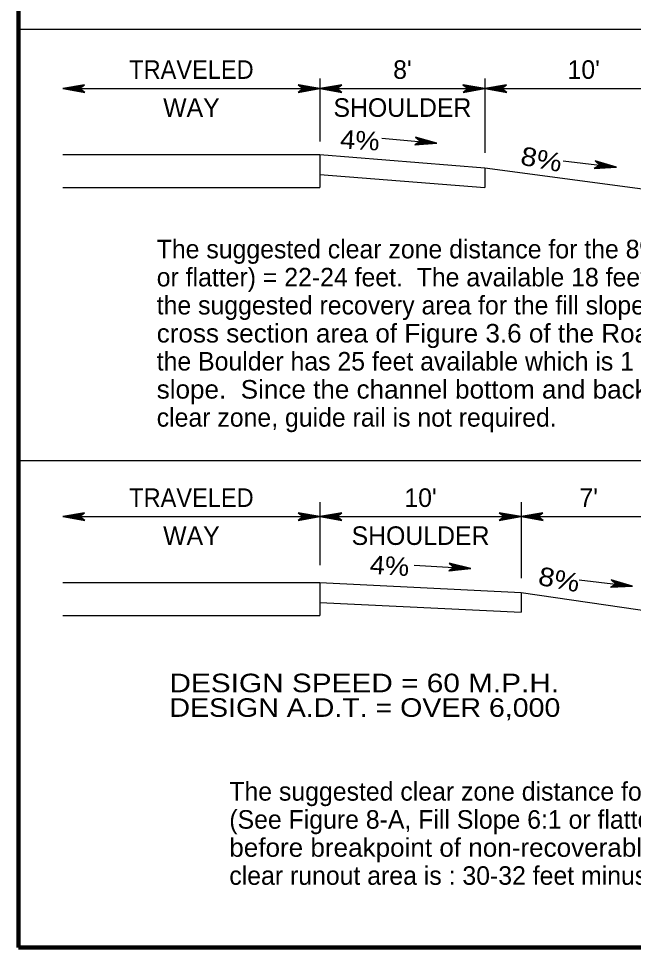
# Model space of a CAD drawing. Extents: x -15.691 to -15.016, y -14.8 to -13.916.
# Drawn here: x -15.6451 to -15.3861, y -14.7538 to -14.3626 of the extents above; entities that cross this region are included whole.
import ezdxf
from ezdxf.enums import TextEntityAlignment as Align

# ---------------------------------------------------------------- set-up
doc = ezdxf.new("R2010")
doc.units = 0
doc.header["$LTSCALE"] = 0.0031
for name, color, linetype, lineweight in [('1', 7, 'Continuous', 90), ('24', 7, 'Continuous', 25), ('5', 7, 'Continuous', 25)]:
    doc.layers.add(name, color=color, linetype=linetype, lineweight=lineweight)

msp = doc.modelspace()

# ---------------------------------------------------------------- linework, layer by layer
at = {"layer": '1'}
for p, q in [((-15.645142, -14.753775), (-15.645142, -13.962108)), ((-15.645142, -14.753775), (-15.645142, -13.962108)), ((-15.061808, -14.753775), (-15.645142, -14.753775))]:
    msp.add_line(p, q, dxfattribs=at)
at = {"layer": '24'}
for p, q in [((-15.518158, -14.387742), (-15.518158, -14.414308)), ((-15.448717, -14.387742), (-15.448717, -14.419075)), ((-15.492058, -14.412942), (-15.4689, -14.414983)), ((-15.415775, -14.422475), (-15.3933, -14.4252)), ((-15.518158, -14.5662), (-15.518158, -14.592758)), ((-15.433433, -14.5662), (-15.433433, -14.598208)), ((-15.626492, -14.572342), (-15.518158, -14.572342)), ((-15.478433, -14.592758), (-15.4546, -14.594125)), ((-15.408967, -14.598892), (-15.386492, -14.601617))]:
    msp.add_line(p, q, dxfattribs=at)
for points in [[(-15.626492, -14.392042), (-15.61725, -14.393675), (-15.619458, -14.392042), (-15.6173, -14.390433), (-15.626492, -14.392042), (-15.625875, -14.392025), (-15.617508, -14.39355), (-15.619633, -14.392017), (-15.617675, -14.390558), (-15.62555, -14.391992), (-15.625242, -14.392042), (-15.618075, -14.393308), (-15.619683, -14.392017), (-15.618025, -14.390767), (-15.6251, -14.392042), (-15.624792, -14.391992), (-15.618525, -14.393125), (-15.619742, -14.392042), (-15.6185, -14.390908), (-15.6239, -14.391992), (-15.623375, -14.391992), (-15.618992, -14.392892), (-15.619842, -14.392067), (-15.618925, -14.391142), (-15.623283, -14.392042), (-15.622792, -14.392067), (-15.619492, -14.392633), (-15.620125, -14.391992), (-15.619442, -14.391358), (-15.622342, -14.392042), (-15.621875, -14.392083), (-15.619892, -14.392467), (-15.620217, -14.392017), (-15.619675, -14.391525), (-15.621633, -14.392042), (-15.620342, -14.392342), (-15.620525, -14.391992), (-15.619958, -14.391642), (-15.621308, -14.391992), (-15.620458, -14.3922), (-15.620817, -14.391925), (-15.620408, -14.391758), (-15.620817, -14.392017), (-15.6206, -14.392067)], [(-15.626492, -14.392042), (-15.518158, -14.392042), (-15.448717, -14.392042)], [(-15.518158, -14.392042), (-15.5274, -14.390408), (-15.525192, -14.392042), (-15.52735, -14.39365), (-15.518158, -14.392042), (-15.518775, -14.392058), (-15.527142, -14.390525), (-15.525017, -14.392058), (-15.526975, -14.393517), (-15.5191, -14.392083), (-15.519408, -14.392042), (-15.526583, -14.390767), (-15.524975, -14.392058), (-15.526625, -14.393308), (-15.51955, -14.392042), (-15.519858, -14.392083), (-15.526125, -14.39095), (-15.524908, -14.392042), (-15.52615, -14.393167), (-15.52075, -14.392083), (-15.521275, -14.392083), (-15.525658, -14.391183), (-15.524808, -14.392008), (-15.525725, -14.392933), (-15.521367, -14.392042), (-15.521858, -14.392008), (-15.525158, -14.391442), (-15.524525, -14.392083), (-15.525208, -14.392717), (-15.522317, -14.392042), (-15.522775, -14.391992), (-15.524758, -14.391617), (-15.524433, -14.392058), (-15.524975, -14.39255), (-15.523017, -14.392033), (-15.524308, -14.391733), (-15.524125, -14.392083), (-15.524692, -14.392442), (-15.523342, -14.392083), (-15.524192, -14.391875), (-15.523833, -14.39215), (-15.524242, -14.392317), (-15.523842, -14.392058), (-15.52405, -14.392008)], [(-15.518158, -14.392042), (-15.508917, -14.393675), (-15.511125, -14.392042), (-15.508967, -14.390433), (-15.518158, -14.392042), (-15.517542, -14.392025), (-15.509175, -14.39355), (-15.5113, -14.392017), (-15.509342, -14.390558), (-15.517217, -14.391992), (-15.516908, -14.392042), (-15.509742, -14.393308), (-15.51135, -14.392017), (-15.509692, -14.390767), (-15.516767, -14.392042), (-15.516458, -14.391992), (-15.510192, -14.393125), (-15.511408, -14.392042), (-15.510167, -14.390908), (-15.515567, -14.391992), (-15.515042, -14.391992), (-15.510658, -14.392892), (-15.511508, -14.392067), (-15.510592, -14.391142), (-15.51495, -14.392042), (-15.514458, -14.392067), (-15.511158, -14.392633), (-15.511792, -14.391992), (-15.511108, -14.391358), (-15.514008, -14.392042), (-15.513542, -14.392083), (-15.511558, -14.392467), (-15.511883, -14.392017), (-15.511342, -14.391525), (-15.5133, -14.392042), (-15.512008, -14.392342), (-15.512192, -14.391992), (-15.511625, -14.391642), (-15.512975, -14.391992), (-15.512125, -14.3922), (-15.512483, -14.391925), (-15.512075, -14.391758), (-15.512475, -14.392017), (-15.512267, -14.392067)], [(-15.448717, -14.392042), (-15.457958, -14.390408), (-15.45575, -14.392042), (-15.457908, -14.39365), (-15.448717, -14.392042), (-15.449325, -14.392058), (-15.457692, -14.390525), (-15.455575, -14.392058), (-15.457533, -14.393517), (-15.449658, -14.392083), (-15.449967, -14.392042), (-15.457133, -14.390767), (-15.455525, -14.392058), (-15.457183, -14.393308), (-15.450108, -14.392042), (-15.450417, -14.392083), (-15.456683, -14.39095), (-15.455458, -14.392042), (-15.456708, -14.393167), (-15.451308, -14.392083), (-15.451825, -14.392083), (-15.456217, -14.391183), (-15.455358, -14.392008), (-15.456283, -14.392933), (-15.451925, -14.392042), (-15.452417, -14.392008), (-15.455717, -14.391442), (-15.455083, -14.392083), (-15.455767, -14.392717), (-15.452867, -14.392042), (-15.453333, -14.391992), (-15.455317, -14.391617), (-15.454992, -14.392058), (-15.455525, -14.39255), (-15.453575, -14.392033), (-15.454867, -14.391733), (-15.454683, -14.392083), (-15.45525, -14.392442), (-15.4539, -14.392083), (-15.45475, -14.391875), (-15.454392, -14.39215), (-15.4548, -14.392317), (-15.454392, -14.392058), (-15.454608, -14.392008)], [(-15.448717, -14.392042), (-15.439475, -14.393675), (-15.441683, -14.392042), (-15.439525, -14.390433), (-15.448717, -14.392042), (-15.4481, -14.392025), (-15.439733, -14.39355), (-15.441858, -14.392017), (-15.439892, -14.390558), (-15.447767, -14.391992), (-15.447458, -14.392042), (-15.440292, -14.393308), (-15.4419, -14.392017), (-15.44025, -14.390767), (-15.447325, -14.392042), (-15.447017, -14.391992), (-15.44075, -14.393125), (-15.441967, -14.392042), (-15.440725, -14.390908), (-15.446125, -14.391992), (-15.4456, -14.391992), (-15.441217, -14.392892), (-15.442067, -14.392067), (-15.44115, -14.391142), (-15.445508, -14.392042), (-15.445017, -14.392067), (-15.441717, -14.392633), (-15.44235, -14.391992), (-15.441658, -14.391358), (-15.444558, -14.392042), (-15.444092, -14.392083), (-15.442117, -14.392467), (-15.442442, -14.392017), (-15.4419, -14.391525), (-15.44385, -14.392042), (-15.442558, -14.392342), (-15.44275, -14.391992), (-15.442183, -14.391642), (-15.443525, -14.391992), (-15.442683, -14.3922), (-15.443033, -14.391925), (-15.442625, -14.391758), (-15.443033, -14.392017), (-15.442825, -14.392067)], [(-15.448717, -14.392042), (-15.365383, -14.392042), (-15.313992, -14.392042)], [(-15.4689, -14.414983), (-15.477958, -14.41255), (-15.475908, -14.414367), (-15.4782, -14.415783), (-15.4689, -14.414983), (-15.469517, -14.41495), (-15.477717, -14.412692), (-15.475733, -14.4144), (-15.477817, -14.415683), (-15.46985, -14.41495), (-15.47015, -14.414875), (-15.477175, -14.412975), (-15.475692, -14.414408), (-15.47745, -14.415508), (-15.470292, -14.414867), (-15.4706, -14.414883), (-15.476742, -14.413208), (-15.475625, -14.414392), (-15.476958, -14.415408), (-15.471492, -14.414808), (-15.472008, -14.414758), (-15.4763, -14.413475), (-15.475517, -14.414375), (-15.476517, -14.415208), (-15.472092, -14.414708), (-15.472583, -14.414633), (-15.475825, -14.413783), (-15.475242, -14.414475), (-15.475983, -14.415042), (-15.473042, -14.414625), (-15.4735, -14.414533), (-15.475442, -14.413983), (-15.47515, -14.414458), (-15.475733, -14.4149), (-15.473742, -14.414558), (-15.475, -14.414142), (-15.47485, -14.414508), (-15.475442, -14.414808), (-15.474067, -14.414575), (-15.4749, -14.414292), (-15.474567, -14.4146), (-15.474983, -14.414733), (-15.474558, -14.414508), (-15.474767, -14.414442)], [(-15.3933, -14.4252), (-15.402275, -14.422467), (-15.400283, -14.424358), (-15.402617, -14.425692), (-15.3933, -14.4252), (-15.393908, -14.42515), (-15.402033, -14.422625), (-15.400117, -14.4244), (-15.402233, -14.425608), (-15.394242, -14.425133), (-15.394542, -14.42505), (-15.401508, -14.422925), (-15.400067, -14.4244), (-15.401858, -14.42545), (-15.394683, -14.425033), (-15.394992, -14.425042), (-15.401075, -14.423167), (-15.4, -14.424392), (-15.401367, -14.425358), (-15.395883, -14.424933), (-15.3964, -14.424875), (-15.400642, -14.423458), (-15.3999, -14.424375), (-15.400917, -14.425175), (-15.396483, -14.424817), (-15.396967, -14.424733), (-15.400175, -14.423775), (-15.399625, -14.424483), (-15.400383, -14.425025), (-15.397425, -14.4247), (-15.397883, -14.4246), (-15.3998, -14.423983), (-15.399533, -14.424467), (-15.400125, -14.424892), (-15.398125, -14.424617), (-15.399367, -14.424158), (-15.399225, -14.424533), (-15.399833, -14.424817), (-15.39845, -14.424625), (-15.399267, -14.424317), (-15.39895, -14.424633), (-15.399375, -14.42475), (-15.398942, -14.424542), (-15.39915, -14.424467)], [(-15.626492, -14.572342), (-15.61725, -14.573975), (-15.619458, -14.572342), (-15.6173, -14.570733), (-15.626492, -14.572342), (-15.625875, -14.572317), (-15.617508, -14.57385), (-15.619633, -14.572317), (-15.617675, -14.570858), (-15.62555, -14.572292), (-15.625242, -14.572342), (-15.618075, -14.573608), (-15.619683, -14.572317), (-15.618025, -14.571067), (-15.6251, -14.572342), (-15.624792, -14.572292), (-15.618525, -14.573425), (-15.619742, -14.572342), (-15.6185, -14.571208), (-15.6239, -14.572292), (-15.623375, -14.572292), (-15.618992, -14.573192), (-15.619842, -14.572367), (-15.618925, -14.571442), (-15.623283, -14.572342), (-15.622792, -14.572367), (-15.619492, -14.572933), (-15.620125, -14.572292), (-15.619442, -14.571658), (-15.622342, -14.572342), (-15.621875, -14.572383), (-15.619892, -14.572767), (-15.620217, -14.572317), (-15.619675, -14.571825), (-15.621633, -14.572342), (-15.620342, -14.572642), (-15.620525, -14.572292), (-15.619958, -14.571942), (-15.621308, -14.572292), (-15.620458, -14.5725), (-15.620817, -14.572225), (-15.620408, -14.572058), (-15.620817, -14.572317), (-15.6206, -14.572367)], [(-15.518158, -14.572342), (-15.5274, -14.570708), (-15.525192, -14.572342), (-15.52735, -14.573942), (-15.518158, -14.572342), (-15.518775, -14.572358), (-15.527142, -14.570825), (-15.525017, -14.572358), (-15.526975, -14.573817), (-15.5191, -14.572383), (-15.519408, -14.572342), (-15.526583, -14.571067), (-15.524975, -14.572358), (-15.526625, -14.573608), (-15.51955, -14.572333), (-15.519858, -14.572383), (-15.526125, -14.57125), (-15.524908, -14.572333), (-15.52615, -14.573467), (-15.52075, -14.572383), (-15.521275, -14.572383), (-15.525658, -14.571483), (-15.524808, -14.572308), (-15.525725, -14.573233), (-15.521367, -14.572342), (-15.521858, -14.572308), (-15.525158, -14.571742), (-15.524525, -14.572383), (-15.525208, -14.573017), (-15.522317, -14.572342), (-15.522775, -14.572292), (-15.524758, -14.571908), (-15.524433, -14.572358), (-15.524975, -14.57285), (-15.523017, -14.572333), (-15.524308, -14.572033), (-15.524125, -14.572383), (-15.524692, -14.572742), (-15.523342, -14.572383), (-15.524192, -14.572175), (-15.523833, -14.57245), (-15.524242, -14.572617), (-15.523842, -14.572358), (-15.52405, -14.572308)], [(-15.518158, -14.572342), (-15.508917, -14.573975), (-15.511125, -14.572342), (-15.508967, -14.570733), (-15.518158, -14.572342), (-15.517542, -14.572317), (-15.509175, -14.57385), (-15.5113, -14.572317), (-15.509342, -14.570858), (-15.517217, -14.572292), (-15.516908, -14.572342), (-15.509742, -14.573608), (-15.51135, -14.572317), (-15.509692, -14.571067), (-15.516767, -14.572342), (-15.516458, -14.572292), (-15.510192, -14.573425), (-15.511408, -14.572342), (-15.510167, -14.571208), (-15.515567, -14.572292), (-15.515042, -14.572292), (-15.510658, -14.573192), (-15.511508, -14.572367), (-15.510592, -14.571442), (-15.51495, -14.572342), (-15.514458, -14.572367), (-15.511158, -14.572933), (-15.511792, -14.572292), (-15.511108, -14.571658), (-15.514008, -14.572342), (-15.513542, -14.572383), (-15.511558, -14.572767), (-15.511883, -14.572317), (-15.511342, -14.571825), (-15.5133, -14.572342), (-15.512008, -14.572642), (-15.512192, -14.572292), (-15.511625, -14.571942), (-15.512975, -14.572292), (-15.512125, -14.5725), (-15.512483, -14.572225), (-15.512075, -14.572058), (-15.512475, -14.572317), (-15.512267, -14.572367)], [(-15.518158, -14.572342), (-15.433433, -14.572342), (-15.376492, -14.572342), (-15.277883, -14.572342), (-15.168158, -14.572342)], [(-15.433433, -14.572342), (-15.442675, -14.570708), (-15.440467, -14.572342), (-15.442625, -14.573942), (-15.433433, -14.572342), (-15.43405, -14.572358), (-15.442417, -14.570825), (-15.4403, -14.572358), (-15.442258, -14.573817), (-15.434383, -14.572383), (-15.434692, -14.572342), (-15.441858, -14.571067), (-15.44025, -14.572358), (-15.4419, -14.573608), (-15.434833, -14.572333), (-15.435133, -14.572383), (-15.4414, -14.57125), (-15.440183, -14.572333), (-15.441425, -14.573467), (-15.436033, -14.572383), (-15.43655, -14.572383), (-15.440942, -14.571483), (-15.440083, -14.572308), (-15.441, -14.573233), (-15.436642, -14.572342), (-15.437133, -14.572308), (-15.440433, -14.571742), (-15.4398, -14.572383), (-15.440492, -14.573017), (-15.437592, -14.572342), (-15.438058, -14.572292), (-15.440033, -14.571908), (-15.439708, -14.572358), (-15.44025, -14.57285), (-15.4383, -14.572333), (-15.439592, -14.572033), (-15.4394, -14.572383), (-15.439967, -14.572742), (-15.438625, -14.572383), (-15.439467, -14.572175), (-15.439117, -14.57245), (-15.439525, -14.572617), (-15.439117, -14.572358), (-15.439333, -14.572308)], [(-15.433433, -14.572342), (-15.4242, -14.573975), (-15.4264, -14.572342), (-15.424242, -14.570733), (-15.433433, -14.572342), (-15.432825, -14.572317), (-15.424458, -14.57385), (-15.426575, -14.572317), (-15.424617, -14.570858), (-15.432492, -14.572292), (-15.432183, -14.572342), (-15.425017, -14.573608), (-15.426625, -14.572317), (-15.424967, -14.571067), (-15.432042, -14.572342), (-15.431733, -14.572292), (-15.425467, -14.573425), (-15.426692, -14.572342), (-15.425442, -14.571208), (-15.430842, -14.572292), (-15.430325, -14.572292), (-15.425933, -14.573192), (-15.426792, -14.572367), (-15.425867, -14.571442), (-15.430233, -14.572342), (-15.429733, -14.572367), (-15.426433, -14.572933), (-15.427075, -14.572292), (-15.426383, -14.571658), (-15.429283, -14.572342), (-15.428817, -14.572383), (-15.426833, -14.572767), (-15.427167, -14.572317), (-15.426625, -14.571825), (-15.428575, -14.572342), (-15.427283, -14.572642), (-15.427467, -14.572292), (-15.4269, -14.571942), (-15.42825, -14.572292), (-15.4274, -14.5725), (-15.427758, -14.572225), (-15.42735, -14.572058), (-15.427758, -14.572317), (-15.427542, -14.572367)], [(-15.4546, -14.594125), (-15.463733, -14.591967), (-15.461617, -14.593725), (-15.463867, -14.5952), (-15.4546, -14.594125), (-15.455208, -14.5941), (-15.463475, -14.5921), (-15.46145, -14.59375), (-15.463483, -14.5951), (-15.455542, -14.594117), (-15.45585, -14.59405), (-15.462933, -14.592367), (-15.4614, -14.59375), (-15.463125, -14.594908), (-15.455992, -14.594042), (-15.4563, -14.594067), (-15.462492, -14.592583), (-15.461333, -14.593733), (-15.462642, -14.594792), (-15.457192, -14.594017), (-15.457708, -14.593992), (-15.462042, -14.592842), (-15.461233, -14.593717), (-15.4622, -14.594583), (-15.4578, -14.593942), (-15.458292, -14.593883), (-15.46155, -14.593133), (-15.460958, -14.593808), (-15.461675, -14.5944), (-15.458742, -14.593883), (-15.459208, -14.593808), (-15.461167, -14.593325), (-15.460867, -14.593783), (-15.461433, -14.59425), (-15.45945, -14.593842), (-15.460725, -14.593467), (-15.460558, -14.593825), (-15.461142, -14.59415), (-15.459775, -14.593875), (-15.460608, -14.593617), (-15.460275, -14.593908), (-15.460692, -14.594058), (-15.460267, -14.593817), (-15.460483, -14.593758)], [(-15.386492, -14.601617), (-15.395467, -14.598883), (-15.393475, -14.600767), (-15.395808, -14.602108), (-15.386492, -14.601617), (-15.3871, -14.601558), (-15.395225, -14.599033), (-15.3933, -14.600808), (-15.395425, -14.602025), (-15.387433, -14.601542), (-15.387733, -14.601467), (-15.394692, -14.599333), (-15.393258, -14.600817), (-15.39505, -14.601858), (-15.387875, -14.601442), (-15.388183, -14.601458), (-15.394267, -14.599575), (-15.393183, -14.6008), (-15.394558, -14.601775), (-15.389067, -14.60135), (-15.389583, -14.601283), (-15.393833, -14.599867), (-15.393083, -14.600792), (-15.394108, -14.601592), (-15.389675, -14.601225), (-15.390158, -14.601142), (-15.393367, -14.600183), (-15.392817, -14.600892), (-15.393575, -14.601442), (-15.390617, -14.601117), (-15.391067, -14.601008), (-15.392992, -14.6004), (-15.392717, -14.600875), (-15.393317, -14.6013), (-15.391317, -14.601025), (-15.392558, -14.600567), (-15.392417, -14.600942), (-15.393025, -14.601225), (-15.391642, -14.601033), (-15.392458, -14.600725), (-15.392142, -14.601042), (-15.392567, -14.601158), (-15.392133, -14.60095), (-15.392333, -14.600875)]]:
    msp.add_lwpolyline(points, dxfattribs=at)
at = {"layer": '5'}
for p, q in [((-15.645142, -14.367008), (-15.061808, -14.367008)), ((-15.626492, -14.419817), (-15.518158, -14.419817)), ((-15.518158, -14.419817), (-15.518158, -14.433708)), ((-15.448717, -14.425375), (-15.448717, -14.433733)), ((-15.518158, -14.428175), (-15.448717, -14.433733)), ((-15.626492, -14.433708), (-15.518158, -14.433708)), ((-15.645142, -14.5487), (-15.061808, -14.5487)), ((-15.626492, -14.600117), (-15.518158, -14.600117)), ((-15.518158, -14.600117), (-15.518158, -14.614008)), ((-15.433433, -14.604283), (-15.433433, -14.612625)), ((-15.518158, -14.608458), (-15.433433, -14.612625)), ((-15.626492, -14.614008), (-15.518158, -14.614008))]:
    msp.add_line(p, q, dxfattribs=at)
for points in [[(-15.518158, -14.419817), (-15.448717, -14.425375), (-15.365383, -14.436483), (-15.267042, -14.385983), (-15.239267, -14.385983)], [(-15.518158, -14.600117), (-15.433433, -14.604283), (-15.376492, -14.612617), (-15.277883, -14.644558), (-15.168158, -14.655675)]]:
    msp.add_lwpolyline(points, dxfattribs=at)

# ---------------------------------------------------------------- texts
at = {"layer": '1', "width": 0.95}
for p in [(-15.572321, -14.38795), (-15.572321, -14.56825)]:
    msp.add_text('TRAVELED', height=0.007817, dxfattribs=at).set_placement(p, align=Align.CENTER)
at = {"layer": '1'}
for s, p in [("8'", (-15.483433, -14.38795)), ("10'", (-15.407054, -14.38795)), ('WAY', (-15.572321, -14.40395)), ('SHOULDER', (-15.483438, -14.40395)), ("10'", (-15.475804, -14.56825)), ("7'", (-15.404967, -14.56825)), ('WAY', (-15.572321, -14.58425)), ('SHOULDER', (-15.475804, -14.58425))]:
    msp.add_text(s, height=0.007817, dxfattribs=at).set_placement(p, align=Align.CENTER)
for s, rotation, width, p in [('4%', 356.566, 1.1, (-15.501567, -14.417686)), ('8%', 349.216, 1.15, (-15.425581, -14.425621)), ('4%', 356.566, 1.1, (-15.489084, -14.596902)), ('8%', 349.216, 1.15, (-15.418123, -14.602604))]:
    msp.add_text(s, height=0.007817, rotation=rotation, dxfattribs=dict(at, width=width)).set_placement(p, align=Align.CENTER)
for s, p in [('The suggested clear zone distance for the 8% slope (See Figure 8-A, Fill Slope, 6:1', (-15.586942, -14.46355)), ('or flatter) = 22-24 feet.  The available 18 feet to the channel is 4 to 6 feet less than', (-15.586942, -14.475367)), ('the suggested recovery area for the fill slope.  The channel is not within the prefer', (-15.586942, -14.487183)), ('the Boulder has 25 feet available which is 1 to 3 feet outside the clear zone for the fill', (-15.586942, -14.510808)), ('clear zone, guide rail is not required.', (-15.586942, -14.534442)), ('The suggested clear zone distance for the 8:1 slope in the clear runout area', (-15.556358, -14.691958)), ('(See Figure 8-A, Fill Slope 6:1 or flatter) = 30-32 feet.  The recovery distance', (-15.556358, -14.703775)), ('clear runout area is : 30-32 feet minus 17 feet = 13 to 15 feet.', (-15.556358, -14.7274))]:
    msp.add_text(s, height=0.007817, dxfattribs=at).set_placement(p)
for s, width, p in [('cross section area of Figure 3.6 of the Roadside Design Guide, AASHTO, 2002.  But', 1.05, (-15.586942, -14.499)), ('slope.  Since the channel bottom and backslope are free of obstructions within the', 1.05, (-15.586942, -14.522625)), ('DESIGN SPEED = 60 M.P.H.', 1.2, (-15.581583, -14.6463)), ('DESIGN A.D.T. = OVER 6,000', 1.15, (-15.581583, -14.656658)), ('before breakpoint of non-recoverable slope = 17 feet.  Therefore the desirable', 1.05, (-15.556358, -14.715592))]:
    msp.add_text(s, height=0.007817, dxfattribs=dict(at, width=width)).set_placement(p)

doc.saveas('drawing.dxf')
